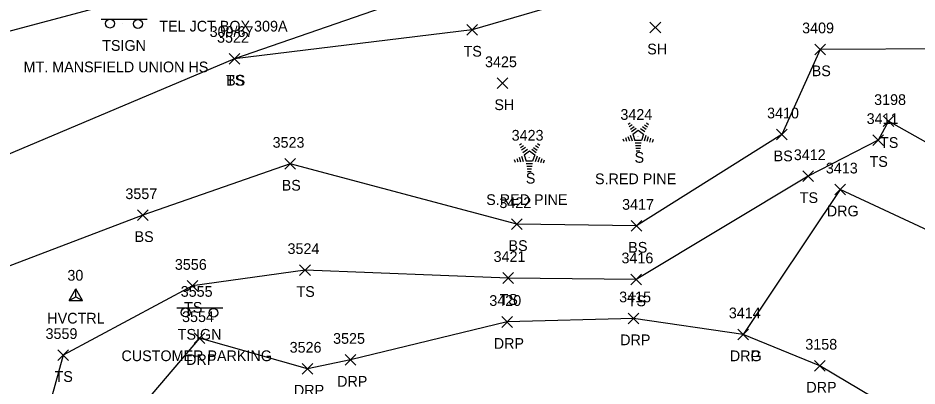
# Model space of a CAD drawing. Extents: x 1520648 to 1523413, y 732854 to 735518.
# Drawn here: x 1521541.1 to 1521708.9, y 733533.8 to 733602.4 of the extents above; entities that cross this region are included whole.
import ezdxf

# ---------------------------------------------------------------- set-up
doc = ezdxf.new("R2010")
doc.units = 0
for name, color, linetype in [('C_A', 7, 'Continuous'), ('C_I', 7, 'Continuous'), ('CPSM', 7, 'Continuous'), ('L_A', 7, 'Continuous'), ('L_C', 7, 'Continuous'), ('L_I', 7, 'Continuous'), ('L_TIC', 7, 'Continuous'), ('LELB', 7, 'Continuous'), ('LTC', 7, 'Continuous'), ('R_A', 7, 'Continuous'), ('R_I', 7, 'Continuous'), ('R_TIC', 7, 'Continuous'), ('RDG', 7, 'Continuous'), ('RDP', 7, 'Continuous'), ('S_A', 7, 'Continuous'), ('S_C', 7, 'Continuous'), ('S_I', 7, 'Continuous'), ('SSGN', 7, 'Continuous'), ('U_C', 7, 'Continuous')]:
    doc.layers.add(name, color=color, linetype=linetype)

msp = doc.modelspace()

# ---------------------------------------------------------------- linework, layer by layer
at = {"layer": 'CPSM'}
for p, q in [((1521550.65, 733549.71), (1521551.9, 733551.88)), ((1521553.15, 733549.71), (1521551.9, 733551.88)), ((1521551.9, 733550.43), (1521551.9, 733551.88)), ((1521550.65, 733549.71), (1521551.9, 733550.43)), ((1521551.9, 733550.43), (1521551.9, 733550.43)), ((1521551.9, 733550.43), (1521553.15, 733549.71)), ((1521550.65, 733549.71), (1521553.15, 733549.71))]:
    msp.add_line(p, q, dxfattribs=at)
at = {"layer": 'L_TIC'}
for points in [[(1521624.88, 733599.21), (1521626.88, 733601.21)], [(1521626.88, 733599.21), (1521624.88, 733601.21)], [(1521659.09, 733599.63), (1521661.09, 733601.63)], [(1521661.09, 733599.63), (1521659.09, 733601.63)], [(1521689.84, 733595.56), (1521691.84, 733597.56)], [(1521691.84, 733595.56), (1521689.84, 733597.56)], [(1521580.54, 733593.8), (1521582.54, 733595.8)], [(1521582.54, 733593.8), (1521580.54, 733595.8)], [(1521580.54, 733593.8), (1521582.54, 733595.8)], [(1521582.54, 733593.8), (1521580.54, 733595.8)], [(1521630.56, 733589.24), (1521632.56, 733591.24)], [(1521632.56, 733589.24), (1521630.56, 733591.24)], [(1521702.63, 733582.19), (1521704.63, 733584.19)], [(1521704.63, 733582.19), (1521702.63, 733584.19)], [(1521702.63, 733582.19), (1521704.63, 733584.19)], [(1521704.63, 733582.19), (1521702.63, 733584.19)], [(1521682.72, 733579.69), (1521684.72, 733581.69)], [(1521684.72, 733579.69), (1521682.72, 733581.69)], [(1521700.66, 733578.65), (1521702.66, 733580.65)], [(1521702.66, 733578.65), (1521700.66, 733580.65)], [(1521590.91, 733574.22), (1521592.91, 733576.22)], [(1521592.91, 733574.22), (1521590.91, 733576.22)], [(1521687.64, 733571.91), (1521689.64, 733573.91)], [(1521689.64, 733571.91), (1521687.64, 733573.91)], [(1521563.43, 733564.64), (1521565.43, 733566.64)], [(1521565.43, 733564.64), (1521563.43, 733566.64)], [(1521633.24, 733562.97), (1521635.24, 733564.97)], [(1521635.24, 733562.97), (1521633.24, 733564.97)], [(1521655.58, 733562.65), (1521657.58, 733564.65)], [(1521657.58, 733562.65), (1521655.58, 733564.65)], [(1521593.7, 733554.4), (1521595.7, 733556.4)], [(1521595.7, 733554.4), (1521593.7, 733556.4)], [(1521631.6, 733552.92), (1521633.6, 733554.92)], [(1521633.6, 733552.92), (1521631.6, 733554.92)], [(1521572.72, 733551.45), (1521574.72, 733553.45)], [(1521574.72, 733551.45), (1521572.72, 733553.45)], [(1521655.52, 733552.66), (1521657.52, 733554.66)], [(1521657.52, 733552.66), (1521655.52, 733554.66)], [(1521548.54, 733538.55), (1521550.54, 733540.55)], [(1521550.54, 733538.55), (1521548.54, 733540.55)]]:
    msp.add_lwpolyline(points, dxfattribs=at)
at = {"layer": 'LELB'}
for points in [[(1521879.84, 733511.18), (1521868.37, 733545.03), (1521852.96, 733582.16), (1521839.72, 733617.96), (1521822.84, 733645.34), (1521811.24, 733661.87), (1521806.64, 733667.18), (1521807.84, 733668.63), (1521807.72, 733669.91), (1521803.6, 733669.51), (1521796.92, 733667.03), (1521791.88, 733664.56), (1521768.96, 733651.98), (1521733.27, 733640.42), (1521696.36, 733629.32), (1521662.08, 733622), (1521619.41, 733620.27), (1521570.74, 733608.28), (1521513.84, 733593.12), (1521446.76, 733575.98), (1521400.95, 733553.88), (1521370.39, 733548.57), (1521314.23, 733532.31)], [(1521871.83, 733519.09), (1521864.71, 733543.86), (1521848.4, 733580.36), (1521835.47, 733616.1), (1521818.38, 733641.09), (1521808.68, 733661.21), (1521805.46, 733665.64), (1521797.46, 733664.46), (1521792.12, 733661.49), (1521769.37, 733650.04), (1521733.75, 733638.1), (1521696.81, 733627.47), (1521663.27, 733618.63), (1521622.81, 733609.07), (1521581.54, 733594.8), (1521522.42, 733569.89), (1521464.29, 733534.94), (1521446.07, 733516.17)], [(1521857.14, 733499.78), (1521863.76, 733516.02), (1521859.15, 733541.28), (1521843.74, 733580), (1521824.84, 733615.66), (1521812.74, 733637.3), (1521799.92, 733657.41), (1521770.97, 733645.75), (1521735.51, 733632.15), (1521697.71, 733621.89), (1521665.54, 733611.79), (1521625.88, 733600.21), (1521581.54, 733594.8)], [(1521715.31, 733596.64), (1521690.84, 733596.56), (1521683.72, 733580.69), (1521656.58, 733563.65), (1521634.24, 733563.97), (1521591.91, 733575.22), (1521564.43, 733565.64), (1521537.4, 733555.4), (1521525.06, 733529.01), (1521514.59, 733499.75), (1521500.4, 733477.49)], [(1521703.63, 733583.19), (1521701.66, 733579.65), (1521688.64, 733572.91), (1521656.52, 733553.66), (1521632.6, 733553.92), (1521594.7, 733555.4), (1521573.72, 733552.45), (1521549.54, 733539.55), (1521543.01, 733515.8), (1521522.63, 733487.47), (1521500.4, 733477.49)], [(1521749.24, 733355.76), (1521768.57, 733384.54), (1521778.63, 733397.02), (1521778.03, 733414.53), (1521789.55, 733433.16), (1521797.65, 733437.08), (1521807.29, 733437.92), (1521812.43, 733455.17), (1521816.31, 733477.33), (1521808.57, 733496.49), (1521793.28, 733514.64), (1521756.08, 733535.47), (1521746.24, 733557.11), (1521726.08, 733570.55), (1521703.63, 733583.19)]]:
    msp.add_lwpolyline(points, dxfattribs=at)
at = {"layer": 'LTC'}
for p, q in [((1521655.02, 733582.62), (1521655.38, 733582.88)), ((1521655.23, 733582.16), (1521655.76, 733582.54)), ((1521655.44, 733581.69), (1521656.15, 733582.2)), ((1521655.65, 733581.23), (1521656.53, 733581.87)), ((1521657.31, 733581.82), (1521658.12, 733581.23)), ((1521657.68, 733582.17), (1521658.36, 733581.67)), ((1521658.05, 733582.52), (1521658.6, 733582.12)), ((1521658.42, 733582.86), (1521658.84, 733582.56)), ((1521654.51, 733580.12), (1521654.72, 733579.47)), ((1521654.97, 733580.34), (1521655.24, 733579.5)), ((1521655.42, 733580.55), (1521655.75, 733579.53)), ((1521655.88, 733580.77), (1521656.89, 733581.51)), ((1521655.88, 733580.77), (1521656.26, 733579.58)), ((1521656.89, 733581.51), (1521657.88, 733580.78)), ((1521657.88, 733580.78), (1521657.49, 733579.58)), ((1521658.32, 733580.51), (1521657.98, 733579.47)), ((1521658.77, 733580.26), (1521658.48, 733579.38)), ((1521659.21, 733580.01), (1521658.97, 733579.28)), ((1521634.72, 733578.74), (1521635.08, 733579)), ((1521634.93, 733578.28), (1521635.46, 733578.66)), ((1521635.14, 733577.81), (1521635.85, 733578.32)), ((1521637.75, 733578.64), (1521638.3, 733578.24)), ((1521638.12, 733578.98), (1521638.54, 733578.68)), ((1521654.05, 733579.9), (1521654.21, 733579.44)), ((1521657.49, 733579.58), (1521656.26, 733579.58)), ((1521657.45, 733579.08), (1521656.31, 733579.08)), ((1521657.37, 733578.58), (1521656.38, 733578.58)), ((1521659.66, 733579.76), (1521659.47, 733579.19)), ((1521635.12, 733576.67), (1521635.45, 733575.65)), ((1521635.35, 733577.35), (1521636.23, 733577.98)), ((1521635.58, 733576.89), (1521636.59, 733577.63)), ((1521635.58, 733576.89), (1521635.96, 733575.7)), ((1521636.59, 733577.63), (1521637.58, 733576.9)), ((1521637.01, 733577.94), (1521637.82, 733577.35)), ((1521637.58, 733576.9), (1521637.19, 733575.7)), ((1521637.38, 733578.29), (1521638.06, 733577.79)), ((1521638.02, 733576.63), (1521637.68, 733575.59)), ((1521657.29, 733578.08), (1521656.46, 733578.08)), ((1521657.2, 733577.58), (1521656.53, 733577.58)), ((1521633.76, 733576.02), (1521633.91, 733575.55)), ((1521634.21, 733576.24), (1521634.42, 733575.59)), ((1521634.67, 733576.46), (1521634.94, 733575.62)), ((1521637.19, 733575.7), (1521635.96, 733575.7)), ((1521637.16, 733575.2), (1521636.01, 733575.2)), ((1521638.47, 733576.38), (1521638.18, 733575.5)), ((1521638.91, 733576.13), (1521638.67, 733575.4)), ((1521639.36, 733575.88), (1521639.17, 733575.31)), ((1521637.07, 733574.7), (1521636.08, 733574.7)), ((1521636.99, 733574.2), (1521636.16, 733574.2)), ((1521636.9, 733573.7), (1521636.23, 733573.7))]:
    msp.add_line(p, q, dxfattribs=at)
at = {"layer": 'R_TIC'}
for points in [[(1521693.61, 733569.42), (1521695.61, 733571.42)], [(1521695.61, 733569.42), (1521693.61, 733571.42)], [(1521631.45, 733544.72), (1521633.45, 733546.72)], [(1521633.45, 733544.72), (1521631.45, 733546.72)], [(1521655.04, 733545.39), (1521657.04, 733547.39)], [(1521657.04, 733545.39), (1521655.04, 733547.39)], [(1521574.01, 733541.71), (1521576.01, 733543.71)], [(1521576.01, 733541.71), (1521574.01, 733543.71)], [(1521675.51, 733542.41), (1521677.51, 733544.41)], [(1521677.51, 733542.41), (1521675.51, 733544.41)], [(1521675.51, 733542.41), (1521677.51, 733544.41)], [(1521677.51, 733542.41), (1521675.51, 733544.41)], [(1521602.2, 733537.65), (1521604.2, 733539.65)], [(1521604.2, 733537.65), (1521602.2, 733539.65)], [(1521689.78, 733536.56), (1521691.78, 733538.56)], [(1521691.78, 733536.56), (1521689.78, 733538.56)], [(1521594.15, 733536), (1521596.15, 733538)], [(1521596.15, 733536), (1521594.15, 733538)]]:
    msp.add_lwpolyline(points, dxfattribs=at)
at = {"layer": 'RDG'}
msp.add_lwpolyline([(1521793.24, 733444), (1521800.86, 733455.25), (1521800.56, 733464.07), (1521801.18, 733479.7), (1521792.16, 733500.04), (1521784.55, 733509.91), (1521756.08, 733535.47), (1521735.24, 733549.65), (1521720.37, 733558.44), (1521694.61, 733570.42), (1521676.51, 733543.41)], dxfattribs=at)
at = {"layer": 'RDP'}
msp.add_lwpolyline([(1521713.69, 733523.9), (1521690.78, 733537.56), (1521676.51, 733543.41), (1521656.04, 733546.39), (1521632.45, 733545.72), (1521603.2, 733538.65), (1521595.15, 733537), (1521575.01, 733542.71), (1521549.07, 733512.22)], dxfattribs=at)
at = {"layer": 'SSGN'}
for p, q in [((1521556.64, 733602.21), (1521565.24, 733602.21)), ((1521560.66, 733601.31), (1521560.66, 733601.31)), ((1521570.75, 733548.34), (1521579.34, 733548.34)), ((1521574.77, 733547.43), (1521574.77, 733547.43))]:
    msp.add_line(p, q, dxfattribs=at)
for centre in [(1521558.3, 733601.38), (1521563.51, 733601.31), (1521572.41, 733547.5), (1521577.62, 733547.43)]:
    msp.add_circle(centre, 0.833, dxfattribs=at)

# ---------------------------------------------------------------- texts
at = {"layer": 'C_A'}
msp.add_text('HVCTRL', height=2, dxfattribs=at).set_placement((1521546.6, 733545.43))
at = {"layer": 'C_I'}
msp.add_text('30', height=2, dxfattribs=at).set_placement((1521550.35, 733553.43))
at = {"layer": 'L_A'}
for s, p in [('TS', (1521624.29, 733595.21)), ('SH', (1521658.58, 733595.63)), ('BS', (1521689.28, 733591.56)), ('TS', (1521579.95, 733589.8)), ('BS', (1521579.98, 733589.8)), ('SH', (1521630.05, 733585.24)), ('TS', (1521702.03, 733578.19)), ('TS', (1521702.03, 733578.19)), ('S', (1521656.21, 733575.42)), ('BS', (1521682.17, 733575.69)), ('TS', (1521700.07, 733574.65)), ('S', (1521635.91, 733571.54)), ('BS', (1521590.35, 733570.22)), ('TS', (1521687.05, 733567.91)), ('BS', (1521562.88, 733560.64)), ('BS', (1521632.68, 733558.97)), ('BS', (1521655.02, 733558.65)), ('TS', (1521593.11, 733550.4)), ('TS', (1521631.01, 733548.92)), ('TS', (1521654.93, 733548.66)), ('TS', (1521572.13, 733547.45)), ('TS', (1521547.95, 733534.55))]:
    msp.add_text(s, height=2, dxfattribs=at).set_placement(p)
at = {"layer": 'L_C'}
for p in [(1521648.83, 733571.42), (1521628.53, 733567.54)]:
    msp.add_text('S.RED PINE', height=2, dxfattribs=at).set_placement(p)
at = {"layer": 'L_I'}
for s, p in [('3409', (1521687.49, 733599.56)), ('3522', (1521578.28, 733597.8)), ('3522', (1521578.28, 733597.8)), ('3425', (1521628.3, 733593.24)), ('3198', (1521700.93, 733586.19)), ('3198', (1521700.93, 733586.19)), ('3424', (1521653.57, 733583.42)), ('3410', (1521680.95, 733583.69)), ('3411', (1521699.53, 733582.65)), ('3523', (1521588.65, 733578.22)), ('3423', (1521633.27, 733579.54)), ('3412', (1521685.94, 733575.91)), ('3557', (1521561.17, 733568.64)), ('3422', (1521630.98, 733566.97)), ('3417', (1521653.89, 733566.65)), ('3524', (1521591.44, 733558.4)), ('3421', (1521629.9, 733556.92)), ('3416', (1521653.77, 733556.66)), ('3556', (1521570.41, 733555.45)), ('3559', (1521546.27, 733542.55))]:
    msp.add_text(s, height=2, dxfattribs=at).set_placement(p)
at = {"layer": 'LTC'}
for p in [(1521656.77, 733580.52), (1521636.47, 733576.64)]:
    msp.add_text('.', height=1.04, rotation=270, dxfattribs=at).set_placement(p)
at = {"layer": 'R_A'}
for s, p in [('DRG', (1521692.1, 733565.42)), ('DRP', (1521653.53, 733541.39)), ('DRP', (1521629.93, 733540.72)), ('DRP', (1521572.5, 733537.71)), ('DRG', (1521674, 733538.41)), ('DRP', (1521674, 733538.41)), ('DRP', (1521600.69, 733533.65)), ('DRP', (1521592.63, 733532)), ('DRP', (1521688.27, 733532.56))]:
    msp.add_text(s, height=2, dxfattribs=at).set_placement(p)
at = {"layer": 'R_I'}
for s, p in [('3413', (1521691.92, 733573.42)), ('3420', (1521629.1, 733548.72)), ('3415', (1521653.34, 733549.39)), ('3414', (1521673.81, 733546.41)), ('3414', (1521673.81, 733546.41)), ('3554', (1521571.75, 733545.71)), ('3525', (1521599.94, 733541.65)), ('3526', (1521591.83, 733540)), ('3158', (1521688.08, 733540.56))]:
    msp.add_text(s, height=2, dxfattribs=at).set_placement(p)
at = {"layer": 'S_A'}
for p in [(1521556.84, 733596.29), (1521570.94, 733542.42)]:
    msp.add_text('TSIGN', height=2, dxfattribs=at).set_placement(p)
at = {"layer": 'S_C'}
for s, p in [('MT. MANSFIELD UNION HS', (1521542.17, 733592.29)), ('CUSTOMER PARKING', (1521560.44, 733538.42))]:
    msp.add_text(s, height=2, dxfattribs=at).set_placement(p)
at = {"layer": 'S_I'}
msp.add_text('3555', height=2, dxfattribs=at).set_placement((1521571.5, 733550.42))
at = {"layer": 'U_C'}
for s, p in [('TEL JCT BOX 309A', (1521567.51, 733599.89)), ('309/67', (1521576.9, 733598.88))]:
    msp.add_text(s, height=2, dxfattribs=at).set_placement(p)

doc.saveas('drawing.dxf')
